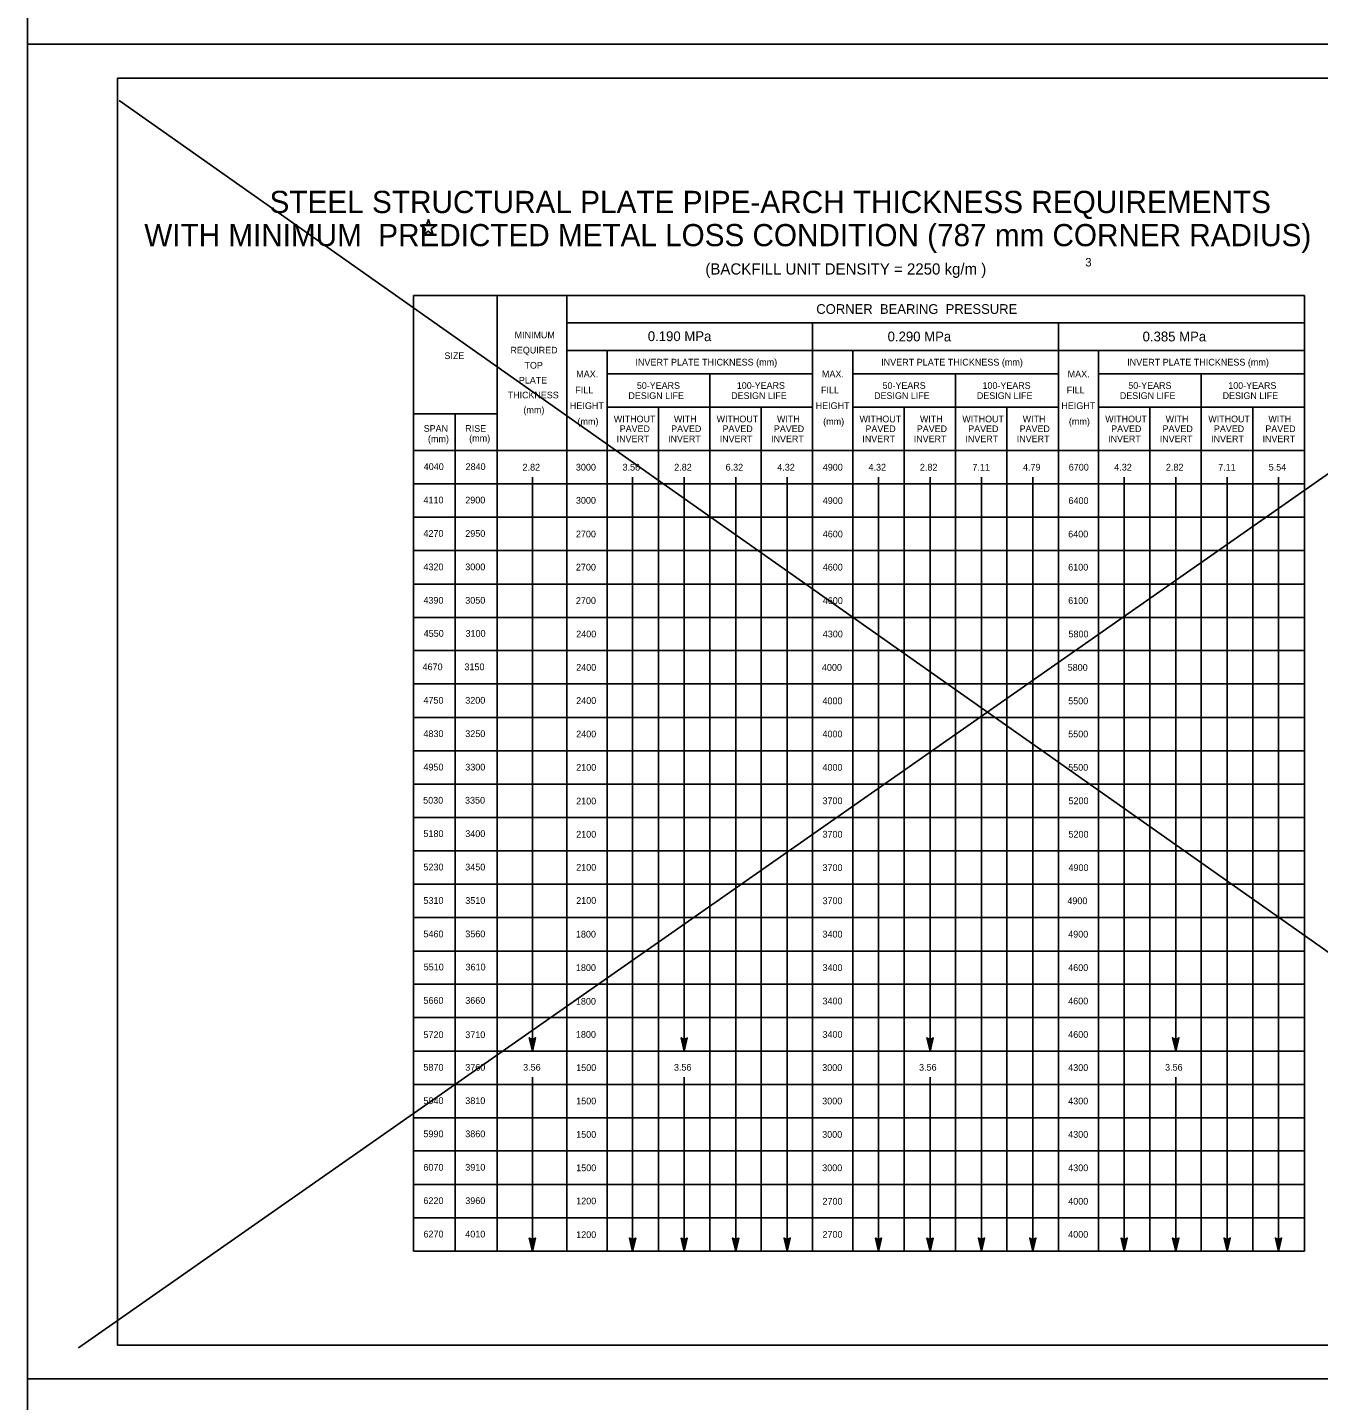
# Model space of a CAD drawing. Extents: x 591 to 2288, y -189 to 2187.
# Drawn here: x 591 to 1166, y 396 to 1007 of the extents above; entities that cross this region are included whole.
import ezdxf

# ---------------------------------------------------------------- set-up
doc = ezdxf.new("R2010")
doc.units = 0
for name, color, linetype in [('1', 7, 'Continuous'), ('2', 7, 'Continuous'), ('PLT-BNDY', 7, 'Continuous')]:
    doc.layers.add(name, color=color, linetype=linetype)

msp = doc.modelspace()

# ---------------------------------------------------------------- linework, layer by layer
at = {"layer": '1'}
for p, q in [((1414.15, 978.73), (614.04, 418.99)), ((632.22, 974.18), (1445.97, 400.79))]:
    msp.add_line(p, q, dxfattribs=at)
at = {"layer": '2'}
for p, q in [((631.34, 420.21), (631.34, 984.21)), ((631.34, 984.21), (1417.34, 984.21)), ((780.09, 917.46), (780.09, 917.46)), ((763.21, 887.46), (1159.71, 887.46)), ((763.21, 887.46), (763.21, 461.96)), ((800.34, 887.46), (800.34, 461.96)), ((831.46, 887.46), (831.46, 461.96)), ((1159.71, 887.46), (1159.71, 461.96)), ((831.46, 875.21), (1159.71, 875.21)), ((940.84, 875.21), (940.84, 461.96)), ((1050.21, 875.21), (1050.21, 461.96)), ((831.46, 862.96), (940.84, 862.96)), ((849.34, 862.96), (849.34, 461.96)), ((940.84, 862.96), (1050.21, 862.96)), ((958.71, 862.96), (958.71, 461.96)), ((1050.21, 862.96), (1159.71, 862.96)), ((1068.09, 862.96), (1068.09, 461.96)), ((849.34, 852.59), (940.84, 852.59)), ((895.09, 852.59), (895.09, 461.96)), ((958.71, 852.59), (1050.21, 852.59)), ((1004.46, 852.59), (1004.46, 461.96)), ((1068.09, 852.59), (1159.71, 852.59)), ((1113.84, 852.59), (1113.84, 461.96)), ((849.34, 837.71), (895.09, 837.71)), ((872.21, 837.71), (872.21, 461.96)), ((940.84, 837.71), (895.09, 837.71)), ((917.96, 837.71), (917.96, 461.96)), ((958.71, 837.71), (1004.46, 837.71)), ((981.59, 837.71), (981.59, 461.96)), ((1050.21, 837.71), (1004.46, 837.71)), ((1027.34, 837.71), (1027.34, 461.96)), ((1068.09, 837.71), (1113.84, 837.71)), ((1090.96, 837.71), (1090.96, 461.96)), ((1159.71, 837.71), (1113.84, 837.71)), ((1136.71, 837.71), (1136.71, 461.96)), ((800.34, 834.71), (763.21, 834.71)), ((781.71, 834.71), (781.71, 461.96)), ((1159.71, 818.34), (763.21, 818.34)), ((763.21, 803.59), (1159.71, 803.59)), ((816.09, 806.59), (816.09, 551.09)), ((860.71, 806.59), (860.71, 464.96)), ((883.59, 806.59), (883.59, 551.09)), ((906.59, 806.59), (906.59, 464.96)), ((929.46, 806.59), (929.46, 464.96)), ((970.09, 806.59), (970.09, 464.96)), ((993.09, 806.59), (993.09, 551.09)), ((1015.96, 806.59), (1015.96, 464.96)), ((1038.84, 806.59), (1038.84, 464.96)), ((1079.46, 806.59), (1079.46, 464.96)), ((1102.46, 806.59), (1102.46, 551.09)), ((1125.34, 806.59), (1125.34, 464.96)), ((1148.21, 806.59), (1148.21, 464.96)), ((763.21, 788.71), (1159.71, 788.71)), ((763.21, 773.84), (1159.71, 773.84)), ((763.21, 758.96), (1159.71, 758.96)), ((763.21, 744.09), (1159.71, 744.09)), ((763.21, 729.34), (1159.71, 729.34)), ((763.21, 714.46), (1159.71, 714.46)), ((763.21, 699.59), (1159.71, 699.59)), ((763.21, 684.71), (1159.71, 684.71)), ((763.21, 669.84), (1159.71, 669.84)), ((763.21, 655.09), (1159.71, 655.09)), ((763.21, 640.21), (1159.71, 640.21)), ((763.21, 625.34), (1159.71, 625.34)), ((763.21, 610.46), (1159.71, 610.46)), ((763.21, 595.59), (1159.71, 595.59)), ((763.21, 580.84), (1159.71, 580.84)), ((763.21, 565.96), (1159.71, 565.96)), ((763.21, 551.09), (1159.71, 551.09)), ((816.09, 464.96), (816.09, 539.46)), ((883.59, 464.96), (883.59, 539.46)), ((993.09, 464.96), (993.09, 539.46)), ((1102.46, 464.96), (1102.46, 539.46)), ((763.21, 536.21), (1159.71, 536.21)), ((763.21, 521.34), (1159.71, 521.34)), ((763.21, 506.59), (1159.71, 506.59)), ((763.21, 491.71), (1159.71, 491.71)), ((763.21, 476.84), (1159.71, 476.84)), ((763.21, 461.96), (1159.71, 461.96)), ((1417.34, 420.21), (631.34, 420.21))]:
    msp.add_line(p, q, dxfattribs=at)
for points in [[(766.21, 918.71), (768.96, 918.71), (769.84, 921.21), (770.59, 918.59), (773.34, 918.71), (771.09, 917.09), (771.96, 914.46), (769.71, 916.09), (767.59, 914.46), (768.46, 917.09), (766.21, 918.71)], [(817.09, 556.71), (816.46, 556.46), (816.09, 551.09), (817.09, 556.71), (817.46, 556.96), (816.09, 551.09), (815.71, 556.46), (815.09, 556.71), (816.09, 551.09), (814.71, 556.96), (815.09, 556.71)], [(884.71, 556.71), (884.09, 556.46), (883.59, 551.09), (884.71, 556.71), (884.96, 556.96), (883.59, 551.09), (883.21, 556.46), (882.71, 556.71), (883.59, 551.09), (882.34, 556.96), (882.71, 556.71)], [(994.09, 556.71), (993.46, 556.46), (993.09, 551.09), (994.09, 556.71), (994.46, 556.96), (993.09, 551.09), (992.59, 556.46), (992.09, 556.71), (993.09, 551.09), (991.71, 556.96), (992.09, 556.71)], [(1103.46, 556.71), (1102.84, 556.46), (1102.46, 551.09), (1103.46, 556.71), (1103.84, 556.96), (1102.46, 551.09), (1102.09, 556.46), (1101.46, 556.71), (1102.46, 551.09), (1101.09, 556.96), (1101.46, 556.71)], [(817.09, 467.59), (816.46, 467.34), (816.09, 461.96), (817.09, 467.59), (817.46, 467.84), (816.09, 461.96), (815.71, 467.34), (815.09, 467.59), (816.09, 461.96), (814.71, 467.84), (815.09, 467.59)], [(861.71, 467.59), (861.21, 467.34), (860.71, 461.96), (861.71, 467.59), (862.09, 467.84), (860.71, 461.96), (860.34, 467.34), (859.84, 467.59), (860.71, 461.96), (859.34, 467.84), (859.84, 467.59)], [(884.71, 467.59), (884.09, 467.34), (883.59, 461.96), (884.71, 467.59), (884.96, 467.84), (883.59, 461.96), (883.21, 467.34), (882.71, 467.59), (883.59, 461.96), (882.34, 467.84), (882.71, 467.59)], [(907.59, 467.59), (906.96, 467.34), (906.59, 461.96), (907.59, 467.59), (907.96, 467.84), (906.59, 461.96), (906.21, 467.34), (905.59, 467.59), (906.59, 461.96), (905.21, 467.84), (905.59, 467.59)], [(930.46, 467.59), (929.84, 467.34), (929.46, 461.96), (930.46, 467.59), (930.84, 467.84), (929.46, 461.96), (929.09, 467.34), (928.46, 467.59), (929.46, 461.96), (928.09, 467.84), (928.46, 467.59)], [(971.09, 467.59), (970.59, 467.34), (970.09, 461.96), (971.09, 467.59), (971.46, 467.84), (970.09, 461.96), (969.71, 467.34), (969.21, 467.59), (970.09, 461.96), (968.84, 467.84), (969.21, 467.59)], [(994.09, 467.59), (993.46, 467.34), (993.09, 461.96), (994.09, 467.59), (994.46, 467.84), (993.09, 461.96), (992.59, 467.34), (992.09, 467.59), (993.09, 461.96), (991.71, 467.84), (992.09, 467.59)], [(1016.96, 467.59), (1016.34, 467.34), (1015.96, 461.96), (1016.96, 467.59), (1017.34, 467.84), (1015.96, 461.96), (1015.59, 467.34), (1014.96, 467.59), (1015.96, 461.96), (1014.59, 467.84), (1014.96, 467.59)], [(1039.84, 467.59), (1039.21, 467.34), (1038.84, 461.96), (1039.84, 467.59), (1040.21, 467.84), (1038.84, 461.96), (1038.46, 467.34), (1037.84, 467.59), (1038.84, 461.96), (1037.46, 467.84), (1037.84, 467.59)], [(1080.59, 467.59), (1079.96, 467.34), (1079.46, 461.96), (1080.59, 467.59), (1080.84, 467.84), (1079.46, 461.96), (1079.09, 467.34), (1078.59, 467.59), (1079.46, 461.96), (1078.21, 467.84), (1078.59, 467.59)], [(1103.46, 467.59), (1102.84, 467.34), (1102.46, 461.96), (1103.46, 467.59), (1103.84, 467.84), (1102.46, 461.96), (1102.09, 467.34), (1101.46, 467.59), (1102.46, 461.96), (1101.09, 467.84), (1101.46, 467.59)], [(1126.34, 467.59), (1125.71, 467.34), (1125.34, 461.96), (1126.34, 467.59), (1126.71, 467.84), (1125.34, 461.96), (1124.96, 467.34), (1124.34, 467.59), (1125.34, 461.96), (1123.96, 467.84), (1124.34, 467.59)], [(1149.21, 467.59), (1148.59, 467.34), (1148.21, 461.96), (1149.21, 467.59), (1149.59, 467.84), (1148.21, 461.96), (1147.84, 467.34), (1147.21, 467.59), (1148.21, 461.96), (1146.84, 467.84), (1147.21, 467.59)]]:
    msp.add_lwpolyline(points, dxfattribs=at)
at = {"layer": 'PLT-BNDY'}
for points in [[(591.34, 1593.21), (1432.34, 1593.21), (1432.34, 999.21), (591.34, 999.21)], [(591.34, 999.21), (1432.34, 999.21), (1432.34, 405.21), (591.34, 405.21)], [(591.34, 405.21), (1432.34, 405.21), (1432.34, -188.79), (591.34, -188.79)]]:
    msp.add_lwpolyline(points, close=True, dxfattribs=at)

# ---------------------------------------------------------------- texts
at = {"layer": '2'}
for s, height, p in [('STEEL STRUCTURAL PLATE PIPE-ARCH THICKNESS REQUIREMENTS', 9.8993, (699.09, 924.09)), ('WITH MINIMUM  PREDICTED METAL LOSS CONDITION (787 mm CORNER RADIUS)', 9.8752, (643.34, 909.34)), ('(BACKFILL UNIT DENSITY = 2250 kg/m )', 5.0003, (893.09, 896.71)), ('3', 3.75, (1062.21, 900.34)), ('CORNER  BEARING  PRESSURE', 4.3305, (942.46, 879.21)), ('MINIMUM', 2.969, (808.21, 868.34)), ('0.190 MPa', 4.375, (867.46, 867.09)), ('0.290 MPa', 4.375, (974.21, 866.96)), ('0.385 MPa', 4.375, (1087.71, 866.96)), ('SIZE', 2.969, (776.96, 859.09)), ('REQUIRED', 2.969, (806.34, 861.59)), ('TOP', 2.969, (812.59, 854.84)), ('INVERT PLATE THICKNESS (mm)', 3, (861.96, 856.21)), ('INVERT PLATE THICKNESS (mm)', 3, (971.34, 856.21)), ('INVERT PLATE THICKNESS (mm)', 3, (1080.84, 856.21)), ('PLATE', 2.969, (810.09, 848.21)), ('MAX.', 3, (835.59, 850.97)), ('MAX.', 3, (944.96, 850.97)), ('MAX.', 3, (1054.34, 850.97)), ('THICKNESS', 2.969, (805.09, 841.59)), ('FILL', 3, (835.17, 843.84)), ('DESIGN LIFE', 2.9693, (858.84, 841.34)), ('50-YEARS', 2.969, (862.59, 845.84)), ('DESIGN LIFE', 2.9693, (904.59, 841.34)), ('100-YEARS', 2.969, (907.09, 845.84)), ('FILL', 3, (944.55, 843.84)), ('DESIGN LIFE', 2.9693, (968.21, 841.34)), ('50-YEARS', 2.969, (971.96, 845.84)), ('DESIGN LIFE', 2.9693, (1013.96, 841.34)), ('100-YEARS', 2.969, (1016.46, 845.84)), ('FILL', 3, (1053.92, 843.84)), ('DESIGN LIFE', 2.9693, (1077.59, 841.34)), ('50-YEARS', 2.969, (1081.34, 845.84)), ('DESIGN LIFE', 2.9693, (1123.34, 841.34)), ('100-YEARS', 2.969, (1125.84, 845.84)), ('(mm)', 3, (812.09, 834.96)), ('HEIGHT', 3, (832.77, 836.84)), ('HEIGHT', 3, (942.15, 836.84)), ('HEIGHT', 3, (1051.52, 836.84)), ('(mm)', 3, (836.14, 829.84)), ('WITHOUT', 2.969, (852.34, 830.96)), ('WITH', 2.969, (879.09, 830.96)), ('WITHOUT', 2.969, (898.09, 830.96)), ('WITH', 2.969, (924.96, 830.96)), ('(mm)', 3, (945.52, 829.84)), ('WITHOUT', 2.969, (961.71, 830.96)), ('WITH', 2.969, (988.59, 830.96)), ('WITHOUT', 2.969, (1007.46, 830.96)), ('WITH', 2.969, (1034.34, 830.96)), ('(mm)', 3, (1054.89, 829.84)), ('WITHOUT', 2.969, (1071.09, 830.96)), ('WITH', 2.969, (1097.96, 830.96)), ('WITHOUT', 2.969, (1116.96, 830.96)), ('WITH', 2.969, (1143.71, 830.96)), ('SPAN', 2.969, (767.71, 826.71)), ('(mm)', 3, (769.59, 822.09)), ('RISE', 2.969, (786.21, 826.71)), ('(mm)', 3, (787.96, 822.34)), ('PAVED', 2.969, (854.96, 826.59)), ('PAVED', 2.969, (877.84, 826.59)), ('PAVED', 2.969, (900.71, 826.59)), ('PAVED', 2.969, (923.59, 826.59)), ('PAVED', 2.969, (964.34, 826.59)), ('PAVED', 2.969, (987.21, 826.59)), ('PAVED', 2.969, (1010.09, 826.59)), ('PAVED', 2.969, (1032.96, 826.59)), ('PAVED', 2.969, (1073.71, 826.59)), ('PAVED', 2.969, (1096.59, 826.59)), ('PAVED', 2.969, (1119.46, 826.59)), ('PAVED', 2.969, (1142.34, 826.59)), ('INVERT', 2.969, (853.59, 822.09)), ('INVERT', 2.969, (876.46, 822.09)), ('INVERT', 2.969, (899.46, 822.09)), ('INVERT', 2.969, (922.34, 822.09)), ('INVERT', 2.969, (962.96, 822.09)), ('INVERT', 2.969, (985.84, 822.09)), ('INVERT', 2.969, (1008.84, 822.09)), ('INVERT', 2.969, (1031.71, 822.09)), ('INVERT', 2.969, (1072.34, 822.09)), ('INVERT', 2.969, (1095.34, 822.09)), ('INVERT', 2.969, (1118.21, 822.09)), ('INVERT', 2.969, (1141.09, 822.09)), ('4040', 3, (767.71, 809.71)), ('2840', 3, (786.34, 809.71)), ('2.82', 3, (811.71, 809.46)), ('3000', 3, (835.46, 809.46)), ('3.56', 3, (856.21, 809.46)), ('2.82', 3, (879.21, 809.46)), ('6.32', 3, (902.09, 809.46)), ('4.32', 3, (925.09, 809.46)), ('4900', 3, (945.34, 809.46)), ('4.32', 3, (965.71, 809.46)), ('2.82', 3, (988.59, 809.46)), ('7.11', 3, (1011.96, 809.46)), ('4.79', 3, (1034.46, 809.46)), ('6700', 3, (1054.84, 809.46)), ('4.32', 3, (1075.09, 809.46)), ('2.82', 3, (1098.09, 809.46)), ('7.11', 3, (1121.34, 809.46)), ('5.54', 3, (1143.84, 809.46)), ('4110', 3, (767.59, 794.84)), ('2900', 3, (786.21, 794.84)), ('3000', 3, (835.46, 794.71)), ('4900', 3, (945.34, 794.59)), ('6400', 3, (1054.71, 794.59)), ('4270', 3, (767.59, 779.96)), ('2950', 3, (786.21, 779.96)), ('2700', 3, (835.46, 779.71)), ('4600', 3, (945.34, 779.71)), ('6400', 3, (1054.59, 779.71)), ('4320', 3, (767.59, 765.09)), ('3000', 3, (786.21, 765.09)), ('2700', 3, (835.46, 764.96)), ('4600', 3, (945.34, 764.96)), ('6100', 3, (1054.59, 764.96)), ('4390', 3, (767.59, 750.21)), ('3050', 3, (786.21, 750.21)), ('2700', 3, (835.46, 750.09)), ('4600', 3, (945.34, 750.09)), ('6100', 3, (1054.59, 750.09)), ('4550', 3, (767.71, 735.46)), ('3100', 3, (786.34, 735.46)), ('2400', 3, (835.59, 735.21)), ('4300', 3, (945.34, 735.21)), ('5800', 3, (1054.71, 735.21)), ('4670', 3, (767.21, 720.59)), ('3150', 3, (785.84, 720.59)), ('2400', 3, (835.59, 720.34)), ('4000', 3, (944.96, 720.34)), ('5800', 3, (1054.34, 720.34)), ('4750', 3, (767.59, 705.71)), ('3200', 3, (786.21, 705.71)), ('2400', 3, (835.59, 705.59)), ('4000', 3, (945.21, 705.46)), ('5500', 3, (1054.59, 705.46)), ('4830', 3, (767.59, 690.84)), ('3250', 3, (786.21, 690.84)), ('2400', 3, (835.59, 690.71)), ('4000', 3, (945.21, 690.71)), ('5500', 3, (1054.59, 690.71)), ('4950', 3, (767.59, 675.96)), ('3300', 3, (786.21, 675.96)), ('2100', 3, (835.59, 675.84)), ('4000', 3, (945.21, 675.84)), ('5500', 3, (1054.59, 675.84)), ('5030', 3, (767.46, 661.21)), ('3350', 3, (786.09, 661.21)), ('2100', 3, (835.59, 660.84)), ('3700', 3, (945.21, 660.96)), ('5200', 3, (1054.71, 660.96)), ('5180', 3, (767.59, 646.34)), ('3400', 3, (786.21, 646.34)), ('2100', 3, (835.59, 646.09)), ('3700', 3, (945.21, 646.09)), ('5200', 3, (1054.71, 646.09)), ('5230', 3, (767.59, 631.46)), ('3450', 3, (786.21, 631.46)), ('2100', 3, (835.59, 631.34)), ('3700', 3, (945.21, 631.21)), ('4900', 3, (1054.71, 631.21)), ('5310', 3, (767.59, 616.59)), ('3510', 3, (786.21, 616.59)), ('2100', 3, (835.59, 616.59)), ('3700', 3, (945.21, 616.46)), ('4900', 3, (1054.21, 616.46)), ('5460', 3, (767.59, 601.71)), ('3560', 3, (786.21, 601.71)), ('1800', 3, (835.46, 601.59)), ('3400', 3, (945.21, 601.59)), ('4900', 3, (1054.59, 601.59)), ('5510', 3, (767.71, 586.96)), ('3610', 3, (786.34, 586.96)), ('1800', 3, (835.46, 586.71)), ('3400', 3, (945.21, 586.71)), ('4600', 3, (1054.59, 586.71)), ('5660', 3, (767.59, 572.09)), ('3660', 3, (786.21, 572.09)), ('1800', 3, (835.46, 571.71)), ('3400', 3, (945.21, 571.84)), ('4600', 3, (1054.59, 571.84)), ('5720', 3, (767.59, 556.84)), ('3710', 3, (786.21, 556.84)), ('1800', 3, (835.46, 556.96)), ('3400', 3, (945.21, 556.96)), ('4600', 3, (1054.59, 556.96)), ('5870', 3, (767.59, 542.34)), ('3760', 3, (786.21, 542.34)), ('3.56', 3, (811.96, 542.34)), ('1500', 3, (835.59, 542.21)), ('3.56', 3, (879.09, 542.34)), ('3000', 3, (945.09, 542.21)), ('3.56', 3, (988.21, 542.34)), ('4300', 3, (1054.59, 542.21)), ('3.56', 3, (1097.71, 542.34)), ('5940', 3, (767.59, 527.46)), ('3810', 3, (786.21, 527.46)), ('1500', 3, (835.59, 527.34)), ('3000', 3, (945.09, 527.34)), ('4300', 3, (1054.59, 527.34)), ('5990', 3, (767.59, 512.71)), ('3860', 3, (786.21, 512.71)), ('1500', 3, (835.59, 512.46)), ('3000', 3, (945.09, 512.46)), ('4300', 3, (1054.59, 512.46)), ('6070', 3, (767.59, 497.84)), ('3910', 3, (786.21, 497.84)), ('1500', 3, (835.59, 497.59)), ('3000', 3, (945.09, 497.59)), ('4300', 3, (1054.59, 497.59)), ('6220', 3, (767.59, 482.96)), ('3960', 3, (786.21, 482.96)), ('1200', 3, (835.59, 482.84)), ('2700', 3, (945.21, 482.71)), ('4000', 3, (1054.59, 482.71)), ('6270', 3, (767.59, 468.09)), ('4010', 3, (786.21, 468.09)), ('1200', 3, (835.59, 467.84)), ('2700', 3, (945.21, 467.96)), ('4000', 3, (1054.59, 467.96))]:
    msp.add_text(s, height=height, dxfattribs=at).set_placement(p)

doc.saveas('drawing.dxf')
